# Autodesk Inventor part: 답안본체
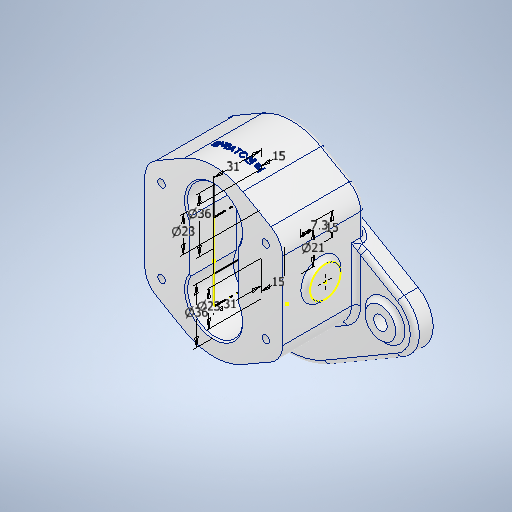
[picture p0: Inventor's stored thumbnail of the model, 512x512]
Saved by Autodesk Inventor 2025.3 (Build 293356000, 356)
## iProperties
Created: 2025-11
Part Number: 답안본체
Material: 알루미늄 6061
Document SubType Name: Modeling
Designer: PC-13
Density: 2.7 g/cm^3
Appearance: 알루미늄 - 평지
Mass: 1253.16 g
Surface Area: 589.991 cm^2
Volume: 464.134 cm^3
Author: PC-13
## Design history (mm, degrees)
sketch "스케치1"
  geometry: L1 (-45, 0)-(-45, 25.238); L2 (-37.5, 38.228)-(-19, 48.909); L3 (19, 48.909)-(37.5, 38.228); L4 (45, 25.238)-(45, 0); L5 (45, 0)-(-45, 0); L6 (-45, 0)-(-45, -25.238); L7 (-37.5, -38.228)-(-19, -48.909); L8 (19, -48.909)-(37.5, -38.228); L9 (45, -25.238)-(45, 0); A1 r 15 centre (-30, 25.238) between (-37.5, 38.228) and (-45, 25.238); A2 r 15 centre (30, 25.238) between (45, 25.238) and (37.5, 38.228); A3 r 15 centre (30, -25.238) between (37.5, -38.228) and (45, -25.238); A4 r 15 centre (-30, -25.238) between (-45, -25.238) and (-37.5, -38.228); A5 r 38 centre (0, 16) between (19, 48.909) and (-19, 48.909); A6 r 38 centre (0, -16) between (-19, -48.909) and (19, -48.909); 8 further points
  constraints: 18 end point, 12 point on circle, 12 point on line, 12 tangent, 6 centre point, 4 equal radius, 3 symmetric about line, 2 midpoint, 2 vertical alignment, 1 equal length, 1 parallel, 1 perpendicular, 1 vertical
  dimensions: "d0" = 90 distance from line of L4 point (-45, 12.619); "d1" = 60 deg angle of L7 L2; "d2" = 60 deg angle of L8 L3; "d3" = 15 radius of A1; "d5" = 38 radius of A5; "d6" = 32 distance of A6.centre A5.centre
extrude "돌출1" new body sketch "스케치1" distance "d7" = 54; taper "d8" = 0 deg
sketch "스케치2"
  geometry: L1 (-73.553, -8.008)-(-26.217, 19.627); L2 (25.786, 19.876)-(74.448, -7.912); L3 (74.448, -42.648)-(25.786, -70.436); L4 (-26.217, -70.187)-(-73.553, -42.552); A1 r 38 centre (0, 16) between (19, 48.909) and (-19, 48.909) reference; A2 r 52 centre (0, -25.28) between (-26.217, 19.627) and (25.786, 19.876); A3 r 15 centre (-30, -25.238) between (-45, -25.238) and (-37.5, -38.228) reference; A4 r 20 centre (-63.469, -25.28) between (-73.553, -8.008) and (-73.553, -42.552); A5 r 20 centre (64.531, -25.28) between (74.448, -42.648) and (74.448, -7.912); A6 r 38 centre (0, -16) between (-19, -48.909) and (19, -48.909) reference; 1 further point
  constraints: 9 point on circle, 8 end point, 8 tangent, 3 centre point, 2 horizontal alignment, 1 vertical alignment
  dimensions: "d77" = 104 diameter of A2; "d81" = 40 diameter of A4; "d82" = 40 diameter of A5; "d83" = 128 distance of A5.centre A4.centre; "d118" = 28.72 distance of point (0, -54) A2.centre
extrude "돌출2" join sketch "스케치2" distance "d35" = 6; taper "d37" = 0 deg; dims "d36" = 6, "d38" = 0
sketch "스케치4"
  geometry: C1 r 25 at (0, -25.28); A1 r 20 centre (-63.469, -25.28) between (-73.553, -8.008) and (-73.553, -42.552) reference; 1 further point
  constraints: 1 centre point, 1 horizontal alignment, 1 vertical alignment
  dimensions: "d39" = 50 diameter of C1
extrude "돌출3" join sketch "스케치4" distance "d41" = 4; taper "d42" = 0 deg
sketch "스케치3"
  geometry: L1 (25.238, 0)-(-25.238, 0) reference; L2 (25.238, 0)-(25.238, -46); L3 (25.238, -46)-(36.738, -46); L4 (36.738, -46)-(36.738, -31); L5 (36.738, -31)-(43.238, -31); L6 (43.238, -31)-(43.238, 0); L7 (-25.238, 0)-(-25.238, -31); L8 (-13.738, -31)-(-7.238, -31); L9 (-7.238, -31)-(-7.238, 0); L10 (-13.738, -31)-(-13.738, -46); L11 (-13.738, -46)-(-14.738, -46); L12 (-25.238, -46)-(-25.238, -31); L13 (-14.738, -46)-(-14.738, -56.7); L14 (-14.738, -56.7)-(-10.238, -56.7); L15 (-25.238, 0)-(-25.238, -54) reference; L16 (-25.238, -46)-(-25.238, -54); L17 (-50.28, -64)-(-0.28, -64) reference; L18 (-25.238, -54)-(-25.238, -64); L19 (-10.238, -64)-(-10.238, -56.7); L20 (43.238, 0)-(25.238, 0); L21 (-7.238, 0)-(-25.238, 0); L22 (-10.238, -64)-(-25.238, -64); L23 (-7.238, 0)-(-25.238, 0); L24 (-10.238, -64)-(-25.238, -64); 2 further points
  constraints: 42 end point, 13 perpendicular, 7 point on line, 4 collinear, 3 vertical, 1 midpoint, 1 parallel
  dimensions: "d18" = 36 diameter of L6 L2; "d19" = 23 diameter of L4 L2; "d21" = 15 distance between parallel lines of L3 L5; "d22" = 36 diameter of L9 L7; "d23" = 31 distance from line of L9.end L5; "d24" = 31 distance between parallel lines of L1 L8; "d25" = 23 diameter of L10 L15; "d26" = 21 diameter of L13 L7; "d28" = 15 distance between parallel lines of L11 L8; "d43" = 7.3 distance between parallel lines of L17 L14; "d44" = 15 distance between parallel lines of L18 L19
revolve "회전1" stored, may be unused: angle "d45" = 360 deg
revolve "회전2" stored, may be unused: angle "d46" = 360 deg
chamfer "모따기3" distance "d53" = 1; stored, may be unused: second distance "d54" = 2, angle "d55" = 45 deg
chamfer "모따기4" distance "d56" = 1; stored, may be unused: second distance "d57" = 2, angle "d58" = 45 deg
sketch "스케치5"
  geometry: L1 (-16, 0)-(16, 0); L2 (-16, 16.991)-(-16, -16.991); L3 (16, 16.991)-(16, -16.991); A1 r 18 centre (0, 25.238) between (-16, 16.991) and (16, 16.991) reference; A2 r 18 centre (0, -25.238) between (16, -16.991) and (-16, -16.991) reference; 1 further point
  constraints: 6 end point, 4 point on circle, 2 vertical, 1 horizontal, 1 midpoint
  dimensions: "d59" = 32 distance of L1.start L1.end
extrude "돌출4" cut sketch "스케치5" distance "d60" = 31; taper "d61" = 0 deg
sketch "스케치6"
  geometry: L1 (-34, 27)-(34, 27); L2 (34, 27)-(34, -27); L3 (34, -27)-(-34, -27); L4 (-34, -27)-(-34, 27); 1 further point
  constraints: 8 end point, 2 parallel, 1 horizontal, 1 perpendicular
  dimensions: "d62" = 68 distance of L1.start L1.end; "d63" = 34 distance from line of L4 point (0, 0); "d64" = 54 distance between parallel lines of L3 L1; "d65" = 27 distance from line of point (0, 0) L1
hole "구멍1" sketch "스케치6" at (-34, 27), (34, 27), (34, -27), (-34, -27) diameter "d66" = 4.917; stored, may be unused: countersink angle "d70" = 90 deg, drill point angle "d72" = 118 deg; dims "d67" = 12, "d68" = 4, "d69" = 2, "d71" = 14
sketch "스케치7"
  geometry: L1 (0, 0)-(0, 50.475) reference; C1 r 10 at (25, 25.238); 2 further points
  constraints: 1 centre point, 1 horizontal alignment, 1 midpoint
  dimensions: "d73" = 20 diameter of C1; "d74" = 25 distance from line of C1.centre L1
extrude "돌출5" join sketch "스케치7" distance "d75" = 3; taper "d76" = 0 deg
sketch "스케치8"
  geometry: C1 r 10 at (0, 0) reference; 2 further points
  constraints: 1 coincident
fillet "모깎기1" dims "d85" = 0.3
chamfer "모따기5" distance "d86" = 0.7; stored, may be unused: second distance "d87" = 2, angle "d88" = 30 deg
fillet "모깎기2" dims "d89" = 3
fillet "모깎기3" dims "d90" = 3
fillet "모깎기4" dims "d91" = 3
sketch "스케치9"
  geometry: C1 r 10 at (-64, -25.28); C2 r 10 at (64, -25.28); C3 r 4.5 at (-64.531, -25.28); C4 r 4.5 at (64, -25.28); A1 r 17 centre (-64.531, -25.28) between (-72.961, -10.517) and (-72.961, -40.043) reference; 2 further points
  constraints: 4 centre point, 2 coincident, 2 horizontal alignment, 1 point on circle
  dimensions: "d92" = 20 diameter of C1; "d93" = 20 diameter of C2; "d94" = 128 distance of C1.centre C2.centre; "d95" = 64 horizontal distance of point (0, 0) C1.centre; "d96" = 9 diameter of C3; "d97" = 9 diameter of C4
extrude "돌출6" join sketch "스케치9" distance "d98" = 3; taper "d99" = 0 deg
extrude "돌출7" cut sketch "스케치9" extent not by distance; stored distance "d100" = 0; taper "d101" = 0 deg
chamfer "모따기6" distance "d102" = 1; stored, may be unused: second distance "d103" = 2, angle "d104" = 45 deg
chamfer "모따기7" distance "d105" = 1; stored, may be unused: second distance "d106" = 2, angle "d107" = 45 deg
node "작업 평면3"
sketch "스케치10"
  geometry: L1 (16.592, -18.402)-(-16.592, -18.402); L2 (-16.592, -18.402)-(-16.592, -13.598); L3 (-16.592, -13.598)-(16.592, -13.598); L4 (16.592, -13.598)-(16.592, -18.402); L5 (-37.5, 0)-(-19, 0) reference; L6 (19, 0)-(-19, 0) reference; 3 further points
  constraints: 1 midpoint, 1 vertical alignment, 2 other
  dimensions: "d108" = 2.40163 distance from line of L1 point (0, -16); "d109" = 16.59159 distance from line of L2 point (0, -16); "d110" = 16 distance from line of L5 point (0, -16)
feature "엠보싱1" sketch "스케치10" dims "d0" = 90, "d1" = 60 deg, "d2" = 60 deg, "d3" = 15, "d5" = 38, "d6" = 32, "d7" = 54, "d111" = 0.5, "d112" = 0
fillet "모깎기5" dims "d113" = 3
fillet "모깎기6" dims "d114" = 3
chamfer "모따기8" distance "d115" = 1; stored, may be unused: second distance "d116" = 2, angle "d117" = 45 deg
node "솔리드1"
mirror "미러1"
feature "A9D066F2-1C7D-4E18-AEED-F7BC21143FA4" dims "d66" = 4.917, "d67" = 12, "d68" = 4, "d69" = 2, "d70" = 90 deg, "d71" = 14, "d72" = 118 deg
other parameters: "d14" = 104, "d30" = 104
